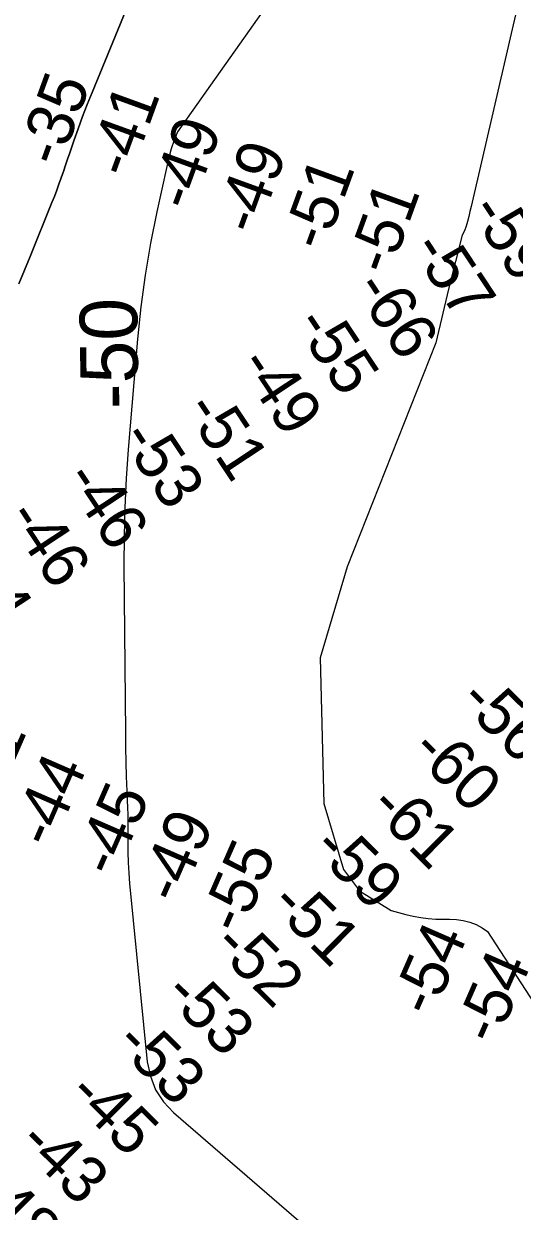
# Model space of a CAD drawing. Extents: x 3271442 to 3309282, y 752266 to 777610.
# Drawn here: x 3291976 to 3292682, y 767420 to 769133 of the extents above; entities that cross this region are included whole.
import ezdxf

# ---------------------------------------------------------------- set-up
doc = ezdxf.new("R2010")
doc.units = 0
for name, color, linetype in [('V-RIVR-RANG', 7, 'Continuous'), ('V-RIVR-RANG-IDEN', 7, 'Continuous'), ('V-TOPO-DPTH', 7, 'Continuous'), ('V-TOPO-MAJR', 7, 'Continuous'), ('V-TOPO-MAJR-IDEN', 7, 'Continuous'), ('V-TOPO-MINR', 7, 'Continuous')]:
    doc.layers.add(name, color=color, linetype=linetype)

msp = doc.modelspace()

# ---------------------------------------------------------------- linework, layer by layer
at = {"layer": 'V-TOPO-DPTH'}
for p, q in [((3292074, 769033.2), (3292177.4, 769285.4)), ((3292074, 769033.2), (3292177.4, 769285.4)), ((3292067.1, 769016), (3292074, 769033.2)), ((3292067.1, 769016), (3292074, 769033.2)), ((3292060.4, 768998.6), (3292067.1, 769016)), ((3292060.4, 768998.6), (3292067.1, 769016)), ((3292054, 768981.2), (3292060.4, 768998.6)), ((3292054, 768981.2), (3292060.4, 768998.6)), ((3292047.8, 768963.6), (3292054, 768981.2)), ((3292047.8, 768963.6), (3292054, 768981.2)), ((3292042, 768946.5), (3292047.8, 768963.6)), ((3292042, 768946.5), (3292047.8, 768963.6)), ((3292038.9, 768937.5), (3292042, 768946.5)), ((3292038.9, 768937.5), (3292042, 768946.5)), ((3292032.7, 768919.4), (3292035.8, 768928.5)), ((3292032.7, 768919.4), (3292035.8, 768928.5)), ((3292035.8, 768928.5), (3292038.9, 768937.5)), ((3292035.8, 768928.5), (3292038.9, 768937.5)), ((3292026.4, 768901.4), (3292029.6, 768910.4)), ((3292026.4, 768901.4), (3292029.6, 768910.4)), ((3292029.6, 768910.4), (3292032.7, 768919.4)), ((3292029.6, 768910.4), (3292032.7, 768919.4)), ((3292019.8, 768883.6), (3292023.2, 768892.5)), ((3292019.8, 768883.6), (3292023.2, 768892.5)), ((3292023.2, 768892.5), (3292026.4, 768901.4)), ((3292023.2, 768892.5), (3292026.4, 768901.4)), ((3291985, 768796.8), (3292016.3, 768874.7)), ((3291985, 768796.8), (3292016.3, 768874.7)), ((3292016.3, 768874.7), (3292019.8, 768883.6)), ((3292016.3, 768874.7), (3292019.8, 768883.6)), ((3291976.9, 768777.1), (3291985, 768796.8)), ((3291976.9, 768777.1), (3291985, 768796.8)), ((3291968.7, 768757.5), (3291976.9, 768777.1)), ((3291968.7, 768757.5), (3291976.9, 768777.1))]:
    msp.add_line(p, q, dxfattribs=at)
at = {"layer": 'V-TOPO-MAJR'}
for p, q in [((3292593.9, 769537.3), (3292197, 768976.8)), ((3292197, 768976.8), (3292192.4, 768964.5)), ((3292192.4, 768964.5), (3292188.2, 768952.1)), ((3292188.2, 768952.1), (3292184.7, 768939.4)), ((3292181.6, 768926.7), (3292167.3, 768861.5)), ((3292184.7, 768939.4), (3292181.6, 768926.7)), ((3292167.3, 768861.5), (3292158.2, 768815.9)), ((3292158.2, 768815.9), (3292150.4, 768770.1)), ((3292150.4, 768770.1), (3292144.4, 768724.1)), ((3292144.4, 768724.1), (3292139.6, 768677.8)), ((3292139.6, 768677.8), (3292126.2, 768518.3)), ((3292126.2, 768518.3), (3292123.3, 768476.7)), ((3292123.3, 768476.7), (3292121.2, 768435)), ((3292121.2, 768435), (3292120.2, 768393.3)), ((3292120.2, 768393.3), (3292120, 768351.6)), ((3292120, 768351.6), (3292122.1, 768109.8)), ((3292122.1, 768109.8), (3292122.4, 768088.8)), ((3292122.4, 768088.8), (3292122.8, 768067.8)), ((3292122.8, 768067.8), (3292123.4, 768046.8)), ((3292123.4, 768046.8), (3292124.2, 768025.8)), ((3292124.2, 768025.8), (3292125.2, 768001.2)), ((3292125.2, 768001.2), (3292125.4, 767992.5)), ((3292125.4, 767992.5), (3292125.6, 767983.8)), ((3292125.6, 767983.8), (3292125.7, 767975)), ((3292125.7, 767966.3), (3292125.5, 767953.3)), ((3292125.7, 767975), (3292125.7, 767966.3)), ((3292125.5, 767953.3), (3292125.6, 767938)), ((3292125.6, 767938), (3292126, 767922.8)), ((3292126, 767922.8), (3292126.9, 767907.6)), ((3292126.9, 767907.6), (3292128.1, 767892.4)), ((3292128.1, 767892.4), (3292153.5, 767635.5)), ((3292153.5, 767635.5), (3292158.1, 767614.6)), ((3292158.1, 767614.6), (3292165.4, 767595.1)), ((3292165.4, 767595.1), (3292177.1, 767577.9)), ((3292177.1, 767577.9), (3292191.5, 767562.1)), ((3292191.5, 767562.1), (3292372.2, 767406.2))]:
    msp.add_line(p, q, dxfattribs=at)
at = {"layer": 'V-TOPO-MINR'}
for p, q in [((3292767.1, 769505.3), (3292620.4, 768869)), ((3292177.4, 769285.4), (3292074, 769033.2)), ((3292074, 769033.2), (3292067.1, 769016)), ((3292067.1, 769016), (3292060.4, 768998.6)), ((3292060.4, 768998.6), (3292054, 768981.2)), ((3292054, 768981.2), (3292047.8, 768963.6)), ((3292047.8, 768963.6), (3292042, 768946.5)), ((3292042, 768946.5), (3292038.9, 768937.5)), ((3292035.8, 768928.5), (3292032.7, 768919.4)), ((3292038.9, 768937.5), (3292035.8, 768928.5)), ((3292029.6, 768910.4), (3292026.4, 768901.4)), ((3292032.7, 768919.4), (3292029.6, 768910.4)), ((3292023.2, 768892.5), (3292019.8, 768883.6)), ((3292026.4, 768901.4), (3292023.2, 768892.5)), ((3292016.3, 768874.7), (3291985, 768796.8)), ((3292019.8, 768883.6), (3292016.3, 768874.7)), ((3292618.7, 768861.8), (3292617, 768854.7)), ((3292620.4, 768869), (3292618.7, 768861.8)), ((3292613.3, 768840.5), (3292610.8, 768833.8)), ((3292615.2, 768847.6), (3292613.3, 768840.5)), ((3292617, 768854.7), (3292615.2, 768847.6)), ((3292607.5, 768827.6), (3292587.6, 768749.6)), ((3292610.8, 768833.8), (3292607.5, 768827.6)), ((3291985, 768796.8), (3291976.9, 768777.1)), ((3291976.9, 768777.1), (3291968.7, 768757.5)), ((3292587.6, 768749.6), (3292569.7, 768672.6)), ((3292569.7, 768672.6), (3292441.5, 768349.1)), ((3292441.5, 768349.1), (3292403, 768218.2)), ((3292403, 768218.2), (3292408.2, 768007.8)), ((3292408.2, 768007.8), (3292436.5, 767912.8)), ((3292436.5, 767912.8), (3292459.6, 767882)), ((3292459.6, 767882), (3292505, 767853.7)), ((3292505, 767853.7), (3292515.5, 767850.6)), ((3292515.5, 767850.6), (3292526.2, 767847.8)), ((3292526.2, 767847.8), (3292536.9, 767845.4)), ((3292536.9, 767845.4), (3292547.7, 767843.4)), ((3292547.7, 767843.4), (3292558.6, 767842)), ((3292558.6, 767842), (3292569.5, 767841.2)), ((3292569.5, 767841.2), (3292580.5, 767840.9)), ((3292580.5, 767840.9), (3292589.4, 767841)), ((3292589.4, 767841), (3292599.2, 767840.5)), ((3292599.2, 767840.5), (3292608.9, 767839.2)), ((3292608.9, 767839.2), (3292618.3, 767836.6)), ((3292618.3, 767836.6), (3292627.6, 767833.3)), ((3292627.6, 767833.3), (3292636.1, 767828.7)), ((3292636.1, 767828.7), (3292643.9, 767823.2)), ((3292643.9, 767823.2), (3292710.9, 767720.6))]:
    msp.add_line(p, q, dxfattribs=at)

# ---------------------------------------------------------------- texts
at = {"layer": 'V-RIVR-RANG'}
for s, rotation, p in [('-35', 69.9895, (3292027.6, 768923.7)), ('-41', 69.9895, (3292128, 768907.3)), ('-49', 69.9895, (3292217.2, 768860)), ('-49', 69.9895, (3292311.1, 768825.5)), ('-51', 69.9895, (3292408.9, 768801.9)), ('-51', 69.9895, (3292502.8, 768767.5)), ('-59', 303.4838, (3292615.8, 768862.7)), ('-57', 303.4838, (3292532.1, 768808)), ('-66', 303.4838, (3292449.7, 768751.2)), ('-55', 303.4838, (3292364.1, 768699.3)), ('-49', 303.4838, (3292282.8, 768641.1)), ('-51', 303.4838, (3292205.6, 768576.4)), ('-53', 303.4838, (3292112.7, 768535.7)), ('-46', 303.4838, (3292032, 768476.4)), ('-46', 303.4838, (3291948.5, 768421.4)), ('-44', 303.4838, (3291865.1, 768366.2)), ('-56', 315.2556, (3292600.2, 768153.8)), ('-51', 66.3941, (3291928.6, 767991.8)), ('-60', 315.2556, (3292530.6, 768082)), ('-44', 66.3941, (3292015.5, 767940.9)), ('-45', 66.3941, (3292106.3, 767899)), ('-61', 315.2556, (3292470.6, 768000.7)), ('-49', 66.3941, (3292198.6, 767860.4)), ('-55', 66.3941, (3292288.5, 767816.5)), ('-59', 315.2556, (3292388.8, 767940.9)), ('-51', 315.2556, (3292328, 767860.3)), ('-54', 66.3941, (3292563.8, 767697.4)), ('-52', 315.2556, (3292245.7, 767801.1)), ('-54', 66.3941, (3292655.4, 767657.1)), ('-53', 315.2556, (3292174.8, 767730.6)), ('-53', 315.2556, (3292104.3, 767659.7)), ('-45', 315.2556, (3292036.4, 767586.2)), ('-43', 315.2556, (3291964.8, 767516.4)), ('-48', 315.2556, (3291896.1, 767443.6))]:
    msp.add_text(s, height=67, rotation=rotation, dxfattribs=at).set_placement(p)
at = {"layer": 'V-RIVR-RANG-IDEN'}
msp.add_text('14 February 2012     W.S.  35.7', height=83, rotation=337.5804, dxfattribs=at).set_placement((3291049.3, 767662.8))
at = {"layer": 'V-TOPO-MAJR-IDEN'}
msp.add_text('-50', height=83, rotation=90.6326, dxfattribs=at).set_placement((3292140.7, 768577.2))

doc.saveas('drawing.dxf')
